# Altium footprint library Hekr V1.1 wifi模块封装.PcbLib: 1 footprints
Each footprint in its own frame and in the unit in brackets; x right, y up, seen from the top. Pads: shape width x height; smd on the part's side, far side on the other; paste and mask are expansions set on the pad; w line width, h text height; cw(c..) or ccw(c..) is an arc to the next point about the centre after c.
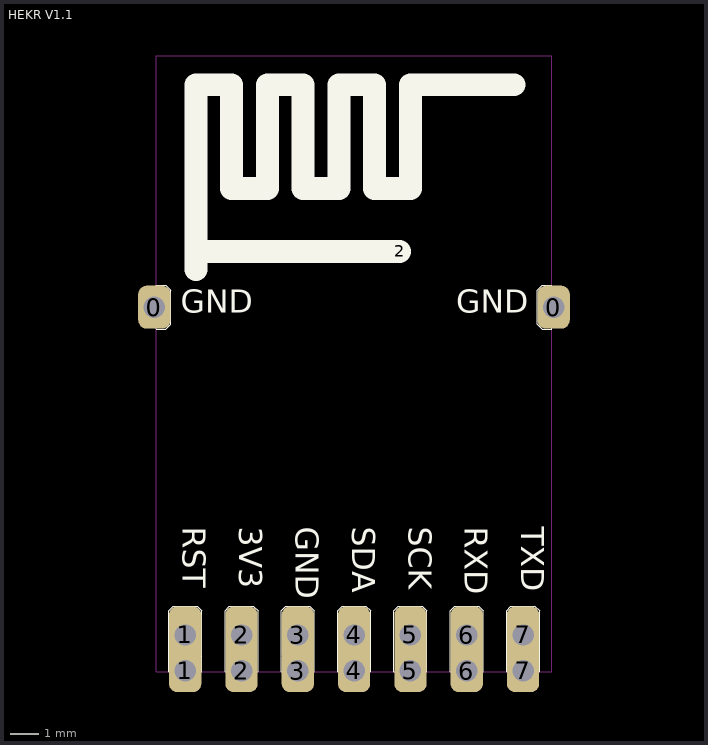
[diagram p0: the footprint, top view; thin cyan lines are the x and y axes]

## HEKR V1.1 [mil]
pads (18):
  rrect50% 45x60 hole 30: 0(35834.86,16090.3) 0(36393.36,16090.3) 1(35878.08,15581.88) 2(35956.82,15581.88) 3(36035.56,15581.88) 4(36114.3,15581.88) 5(36193.04,15581.88) 6(36271.78,15581.88) 7(36350.52,15581.88)
  rrect50% 45x80 hole 30: 1(35878.08,15631.88) 2(35956.82,15631.88) 3(36035.56,15631.88) 4(36114.3,15631.88) 5(36193.04,15631.88) 6(36271.78,15631.88) 7(36350.52,15631.88)
  round 10 on Top Overlay: 1(35892.97,16168.44)
  round 30 on Top Overlay: 2(36177.97,16168.44)
Bottom Layer:
  lines w6: 36356.62,15605.37 36368.05,15616.81
Top Overlay:
  circle w1: c36350.52,15631.88 r14.65
  circle w1: c36271.78,15631.88 r14.65
  circle w1: c36193.04,15631.88 r14.65
  circle w1: c36114.3,15631.88 r14.65
  circle w1: c36035.56,15631.88 r14.65
  circle w1: c35956.82,15631.88 r14.65
  circle w1: c35878.08,15631.88 r14.65
  lines w1: 35837.34,16059.7 35851.11,16059.7 35857.89,16066.48 35857.89,16113.85 35856.84,16114.91 35850.72,16121.03 35837.34,16121.03 ; 35837.34,16059.9 35837.34,16075.86 ccw(c35834.86,16090.3) 35837.32,16104.74 35837.32,16120.88 35837.34,16120.9 ; 35855.04,15580.71 35855.04,15665.66 35861.12,15671.74 35861.61,15672.23 35894.64,15672.23 35901.17,15665.7 35901.17,15580.7 ; 35855.09,15580.71 35863.48,15580.71 ; 35863.47,15580.72 cw(c35878.08,15581.88) 35892.68,15580.68 35900.87,15580.68 35900.9,15580.7 ; 35933.78,15580.71 35933.78,15665.66 35939.86,15671.74 35940.35,15672.23 35973.38,15672.23 35979.91,15665.7 35979.91,15580.7 ; 35933.83,15580.71 35942.22,15580.71 ; 35979.64,15580.7 35979.61,15580.68 35971.42,15580.68 ccw(c35956.82,15581.88) 35942.21,15580.72 ; 36012.52,15580.71 36012.52,15665.66 36018.6,15671.74 36019.09,15672.23 36052.12,15672.23 36058.65,15665.7 36058.65,15580.7 ; 36012.57,15580.71 36020.96,15580.71 ; 36058.38,15580.7 36058.35,15580.68 36050.16,15580.68 ccw(c36035.56,15581.88) 36020.95,15580.72 ; 36091.26,15580.71 36091.26,15665.66 36097.34,15671.74 36097.83,15672.23 36130.86,15672.23 36137.39,15665.7 36137.39,15580.7 ; 36091.31,15580.71 36099.7,15580.71 ; 36170,15580.71 36170,15665.66 36176.08,15671.74 36176.57,15672.23 36209.6,15672.23 36216.13,15665.7 36216.13,15580.7 ; 36170.05,15580.71 36178.44,15580.71 ; 36248.74,15580.71 36248.74,15665.66 36254.82,15671.74 36255.31,15672.23 36288.34,15672.23 36294.87,15665.7 36294.87,15580.7 ; 36248.79,15580.71 36257.18,15580.71 ; 36257.17,15580.72 cw(c36271.78,15581.88) 36286.38,15580.68 36294.57,15580.68 36294.6,15580.7 ; 36327.48,15580.71 36327.48,15665.66 36333.56,15671.74 36334.05,15672.23 36367.08,15672.23 36373.61,15665.7 36373.61,15580.7 ; 36327.53,15580.71 36335.92,15580.71 ; 36373.34,15580.7 36373.31,15580.68 36365.12,15580.68 ccw(c36350.52,15581.88) 36335.91,15580.72 ; 36390.88,16059.57 36377.5,16059.57 36371.38,16065.69 36370.33,16066.74 36370.33,16114.11 36377.12,16120.9 36390.88,16120.9 ; 36390.88,16120.7 36390.88,16104.74 ccw(c36393.36,16090.3) 36390.9,16075.85 36390.9,16059.72 ; 35863.48,15580.71 35863.48,15580.71 ; 35942.22,15580.71 35942.22,15580.71 ; 36020.96,15580.71 36020.96,15580.71 ; 36099.69,15580.72 cw(c36114.3,15581.88) 36128.9,15580.68 36137.09,15580.68 ; 36099.7,15580.71 36099.7,15580.71 ; 36137.09,15580.68 36137.12,15580.7 ; 36178.43,15580.72 cw(c36193.04,15581.88) 36207.64,15580.68 36215.83,15580.68 ; 36178.44,15580.71 36178.44,15580.71 ; 36215.83,15580.68 36215.86,15580.7 ; 36257.18,15580.71 36257.18,15580.71 ; 36335.92,15580.71 36335.92,15580.71 ; 36390.88,16059.7 36390.9,16059.72
  lines w32: 35892.97,16142.86 35892.97,16168.44 ; 36177.97,16168.44 35892.97,16168.44 ; 36337.97,16401.44 36192.97,16401.44 36192.97,16256.44 36142.97,16256.44 36142.97,16401.44 36092.97,16401.44 36092.97,16256.44 36042.97,16256.44 36042.97,16401.44 35992.97,16401.44 35992.97,16256.44 35942.97,16256.44 35942.97,16401.44 35892.97,16401.44 35892.97,16168.44
  text "GND" at 36256.77,16072.19 h55
  text "GND" at 35871.77,16072.19 h55
  text "TXD" at 36337.22,15783.23 h55
  text "RXD" at 36258.34,15783.19 h55
  text "SCK" at 36179.94,15783.23 h55
  text "SDA" at 36101.06,15783.23 h55
  text "GND" at 36022.19,15783.23 h55
  text "3V3" at 35943.31,15783.19 h55
  text "RST" at 35864.43,15783.19 h55
Keep-Out Layer:
  lines w1: 35837.34,16060.02 35837.34,15580.71 35855.09,15580.71 ; 35837.34,16120.67 35837.34,16441.83 36390.89,16441.78 36390.89,16120.86 ; 35901.02,15580.7 35933.74,15580.7 ; 35979.61,15580.69 36012.57,15580.69 ; 36058.55,15580.69 36091.68,15580.68 ; 36136.86,15580.68 36170.39,15580.68 ; 36215.57,15580.67 36248.92,15580.67 ; 36294.62,15580.66 36327.69,15580.66 ; 36373.39,15580.66 36390.89,15580.65 36390.89,16059.6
